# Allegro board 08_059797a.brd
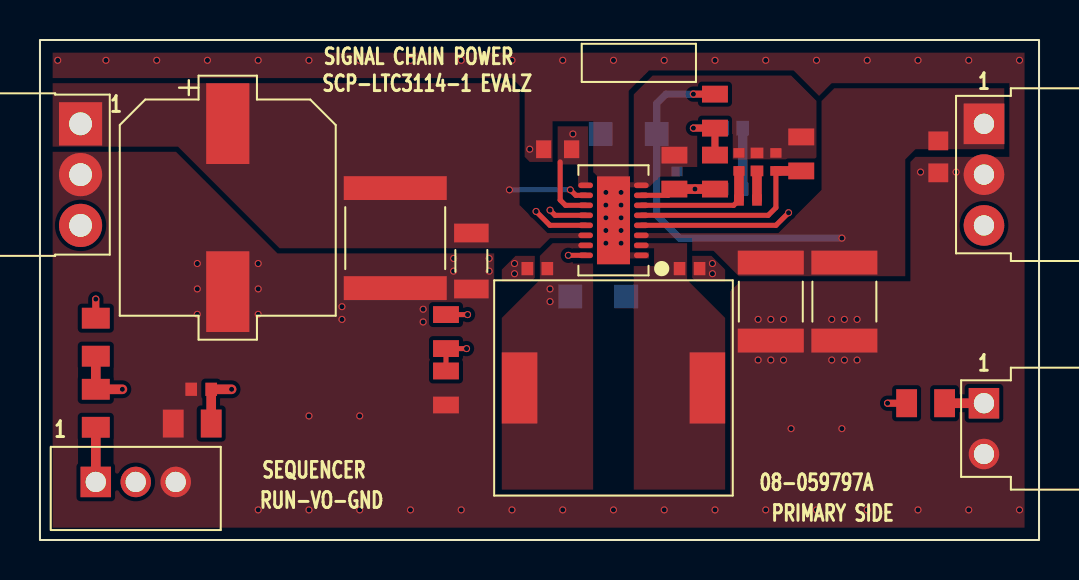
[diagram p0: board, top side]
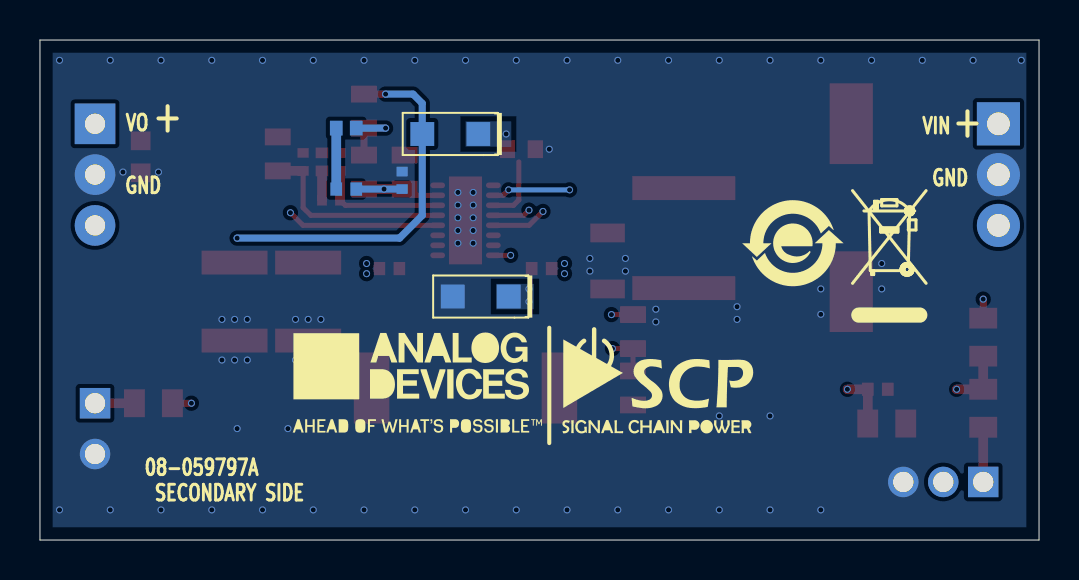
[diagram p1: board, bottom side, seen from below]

Outline 50 x 25 mm; copper layers: TOP, L2_GND, L3_SIGNAL, BOTTOM. Coordinates in mm from the lower left corner of the outline.
Outline path: 0,25 50,25 50,0 0,0 0,25

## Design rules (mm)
constraint set DEFAULT: min track width 0.254

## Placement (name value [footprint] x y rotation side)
C1  68NF  [C0402]  24.89 13.57 180 top
C2  68NF  [C0402]  32.51 13.57 0 top
C3  4.7UF  [C0603]  25.91 19.54 0 top
C4  22UF  [C1812H110]  36.58 11.92 90 top
C5  1UF  [C0603#2]  44.96 19.16 90 top
C6  10uF  [C2220-4]  17.78 15.09 90 top
C7  330UF  [CPLSMSQ406H425]  9.4 16.62 270 top
C8  1uF  [C1206H71]  21.59 13.95 90 top
C9  4700PF  [C0402]  35.43 17 0 top
C10  10PF  [C0402]  34.98 18.9 90 top
C11  0.047UF  [C0402]  36.83 18.9 90 top
C12  1000PF  [C0402]  8.07 7.54 0 top
C13  22UF  [C1812H110]  40.26 11.92 90 top
C14  TBD0402  [C0402]  34.67 17.55 0 bottom
C15  TBD0402  [C0402#2]  31.88 17.98 270 bottom
D1  PMEG2010AEH,115  [SOD123F]  29.46 20.3 0 bottom
D2  PMEG6020ER  [SOD123F]  27.94 12.17 0 bottom
INPUT  PBC03SBAN  [CNTHMHDRRA1X3L300W100H145]  2.03 20.81 270 top
L1  6.8UH  [LSML402W394H201]  28.7 7.6 0 top
NOREF  -  []  90.79 32.31 0 top
NOREF#2  -  []  25.51 46.03 0 top
NOREF#3  -  []  -197.25 -222.03 0 top
NOREF#4  -  []  77.05 131.34 0 top
NOREF#5  -  []  0 0 0 top
NOREF#6  -  []  2.03 20.81 0 top
NOREF#7  -  []  50 25 0 top
NOREF#8  -  []  -197.25 -222.03 0 top
NOREF#9  -  []  0 25 0 top
NOREF#10  -  []  50 0 90 top
NOREF#11  -  []  -137.31 -48.38 0 top
NOREF#12  -  []  0 25 270 top
NOREF#13  -  []  0 0 0 top
NOREF#14  -  []  2.03 20.81 0 top
NOREF#15  -  []  50 0 90 top
NOREF#16  -  []  0 0 0 top
NOREF#17  -  []  50 25 180 top
NOREF#18  -  []  39.83 4.24 0 top
NOREF#19  -  []  0 25 0 top
NOREF#20  -  []  -131.19 155.48 0 top
NOREF#21  -  []  -197.25 -222.03 0 top
NOREF#22  -  []  19.05 7.98 180 bottom
NOREF#23  -  []  7.69 10.93 180 bottom
NOREF#24  -  []  31.4 7.83 180 bottom
NOREF#25  -  []  17.55 11.26 180 bottom
NOREF#26  -  []  12.32 14.84 180 bottom
OUTPUT  PPPC031LGBN-RC  [CNHDRRA1X3H108]  47.24 20.81 270 top
P1  53253-0370  [CNTHMHDR1X3L315W144H224]  2.79 2.9 0 top
R1  2M  [R0805]  33.78 18.4 90 top
R2  499K  [R0805]  31.75 18.4 270 top
R3  10K  [R0805]  38.1 19.3 270 top
R4  27.4K  [R0402]  35.88 18.9 270 top
R5  1MEG  [R0805#2]  2.79 10.14 90 top
R6  0  [R0805#2]  7.62 5.82 0 top
R7  TBD0402  [R0402]  34.67 20.59 180 bottom
R8  49.9  [R0805]  33.78 21.44 90 top
R9  0  [R0805#2]  2.79 6.59 90 top
R10  0  [R0805]  20.32 10.42 270 top
R11  0  [R0805]  20.32 7.6 90 top
R12  0  [R0805#2]  44.32 6.84 0 top
U1  LTC3114MPDHC-1#PBF  [DFN16_5X3_PAD4_4X1_65H31]  28.7 15.98 90 top
VIOC  PPPC021LGBN-RC  [CNTHFHDRRA1X2L220W335H108]  47.24 6.84 270 top

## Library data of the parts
C1 C2 = CAP: User Part Number: UPN; Tolerance: 10; alternate symbols: (); part number: CAP_SM-68NF,16V,10,E035202,C0402; tolerance: 10
C3 = CAP: Tolerance: 10; User Part Number: UPN; alternate symbols: (C0603L_ALT); part number: CAP_SM-4.7UF,6.3V,10,E030256,C0603; tolerance: 10
C4 C13 = CAP: Tolerance: 20; User Part Number: UPN; alternate symbols: (C1812H110L); part number: CAP_SM-22UF,25V,20,E034560,C1812H110; tolerance: 20
C5 = CAP: User Part Number: UPN; Tolerance: 10; alternate symbols: (); part number: CAP_SM-1UF,25V,10,E032748,C0603; tolerance: 10
C6 = CAP: Tolerance: 20; User Part Number: UPN; alternate symbols: (C2220H98L); part number: CAP_SM-10UF,50V,20,E015121,C2220-4; tolerance: 20
C7 = CAPP: User Part Number: UPN; Tolerance: 20; alternate symbols: (); part number: CAPP_SM-330UF,50V,20,E034654,CPLSMSQ406H425; tolerance: 20
C8 = CAP: Tolerance: 10; User Part Number: UPN; alternate symbols: (C1206H71L); part number: CAP_SM-1UF,50V,10,E011257,C1206H71; tolerance: 10
C9 = CAP: User Part Number: UPN; Tolerance: 10; alternate symbols: (C0402L); part number: CAP_SM-4700PF,25V,10,E040088,C0402; tolerance: 10
C10 = CAP: User Part Number: UPN; Tolerance: 5; alternate symbols: (C0402L); part number: CAP_SM-10PF,50V,5,E031797,C0402; tolerance: 5
C11 = CAP: User Part Number: UPN; Tolerance: 10; alternate symbols: (C0402L); part number: CAP_SM-0.047UF,25V,10,E025704,C0402; tolerance: 10
C12 = CAP: User Part Number: UPN; Tolerance: 10; alternate symbols: (); part number: CAP_SM-1000PF,25V,10,E025706,C0402; tolerance: 10
C14 C15 = CAP: User Part Number: UPN; alternate symbols: (C0402L_ALT); part number: CAP_SM-TBD0402,TBD0402,TBD0402,E000381,C0402
D1 = DIOSCHOTTKY: Tolerance: N/A; User Part Number: UPN; alternate symbols: (); part number: DIOSCHOTTKY_SM-PMEG2010AEH,115,20V,N/A,E016182,SOD123F; tolerance: N/A
D2 = DIOSCHOTTKY: Tolerance: N/A; User Part Number: UPN; alternate symbols: (); part number: DIOSCHOTTKY_SM-PMEG6020ER,60V,N/A,E030334,SOD123F; tolerance: N/A
INPUT = CN3P: Tolerance: N/A; User Part Number: UPN; alternate symbols: (CNTHMHDRRA1X3L300W100H145_SCP); part number: CN3P_TH-PBC03SBAN,E034137,CNTHMHDRRA1X3L300W100H145; tolerance: N/A
L1 = IND: Tolerance: 30; User Part Number: UPN; alternate symbols: (); part number: IND_SM-6.8UH,30,E040047,LSML402W394H201; tolerance: 30
OUTPUT = CN3P: User Part Number: UPN; Tolerance: N/A; alternate symbols: (CNHDRRA1X3H108_SCP); part number: CN3P_TH-PPPC031LGBN-RC,E034111,CNHDRRA1X3H108; tolerance: N/A
P1 = CN3P: Tolerance: N/A; User Part Number: UPN; alternate symbols: (); part number: CN3P_TH-53253-0370,E033940,CNTHMHDR1X3L315W144H224; tolerance: N/A
R1 = RES: User Part Number: UPN; Tolerance: 1; alternate symbols: (R0805L); part number: RES_SM-2M,E040097,1/8W,1,R0805; tolerance: 1
R2 = RES: User Part Number: UPN; Tolerance: 1; alternate symbols: (R0805L); part number: RES_SM-499K,E003640,1/8W,1,R0805; tolerance: 1
R3 = RES: User Part Number: UPN; Tolerance: 1; alternate symbols: (R0805L); part number: RES_SM-10K,E003254,1/8W,1,R0805; tolerance: 1
R4 = RES: User Part Number: UPN; Tolerance: 1; alternate symbols: (R0402L); part number: RES_SM-27.4K,E021819,1/10W,1,R0402; tolerance: 1
R5 = RES: User Part Number: UPN; Tolerance: 5; alternate symbols: (); part number: RES_SM-1MEG,E033749,1/8W,5,R0805; tolerance: 5
R6 R9-R12 = RES: User Part Number: UPN; Tolerance: N/A; alternate symbols: (R0805L); part number: RES_SM-0,E030875,1/8W,N/A,R0805; tolerance: N/A
R7 = RES: User Part Number: UPN; alternate symbols: (R0402L,R0402L_ALT); part number: RES_SM-TBD0402,E004049,TBD0402,TBD0402,R0402
R8 = RES: User Part Number: UPN; Tolerance: 1; alternate symbols: (R0805L); part number: RES_SM-49.9,E003412,1/8W,1,R0805; tolerance: 1
U1 = ADLTC3114_1: User Part Number: UPN; Tolerance: N/A; alternate symbols: (); part number: ADLTC3114_1_SM-LTC3114MPDHC-1#PBF,E039955,DFN16_5X3_PAD4_4X1_65H31; tolerance: N/A
VIOC = CN2P: Tolerance: N/A; User Part Number: UPN; alternate symbols: (CNTHFHDRRA1X2L220W335H108_SCP); part number: CN2P_TH-PPPC021LGBN-RC,E034113,CNTHFHDRRA1X2L220W335H108; tolerance: N/A

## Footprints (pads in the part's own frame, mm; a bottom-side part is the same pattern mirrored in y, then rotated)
C0402
  rect 0.584x0.66 smd: 1(-0.5,0) 2(0.5,0)
C0402#2
  rect 0.483x0.559 smd: 1(-0.438,0) 2(0.438,0)
C0603
  rect 0.762x0.889 smd: 1(-0.699,0) 2(0.699,0)
C0603#2
  rect 0.94x0.991 smd: 1(-0.8,0) 2(0.8,0)
C1206H71
  rect 0.94x1.727 smd: 1(-1.4,0) 2(1.4,0)
C1812H110
  rect 1.194x3.302 smd: 1(-1.95,0) 2(1.95,0)
C2220-4
  rect 1.194x5.156 smd: 1(-2.5,0) 2(2.5,0)
CNHDRRA1X3H108
  rect 2.032x2.032 hole 1.016: 1(0,0)
  round 2.032 hole 1.016: 2(2.54,0) 3(5.08,0)
CNTHFHDRRA1X2L220W335H108
  rect 1.524x1.524 hole 1.016: 1(0,0)
  round 1.524 hole 1.016: 2(2.54,0)
CNTHMHDR1X3L315W144H224
  rect 1.524x1.524 hole 1.016: 1(0,0)
  round 1.524 hole 1.016: 2(2,0) 3(4,0)
CNTHMHDRRA1X3L300W100H145
  rect 2.159x2.159 hole 1.143: 1(0,0)
  round 2.159 hole 1.143: 2(2.54,0) 3(5.08,0)
CPLSMSQ406H425
  rect 4.039x2.159 smd: N(4.2,0) P(-4.2,0)
DFN16_5X3_PAD4_4X1_65H31
  oval 0.279x0.737 smd: 1(-1.75,-1.393) 2(-1.25,-1.393) 3(-0.75,-1.393) 4(-0.25,-1.393) 5(0.25,-1.393) 6(0.75,-1.393) 7(1.25,-1.393) 8(1.75,-1.393) 9(1.75,1.393) 10(1.25,1.393) 11(0.75,1.393) 12(0.25,1.393) 13(-0.25,1.393) 14(-0.75,1.393) 15(-1.25,1.393) 16(-1.75,1.393)
  rect 4.394x1.651 smd: PAD(0,0)
LSML402W394H201
  rect 1.778x3.556 smd: 1(-4.7,0) 2(4.7,0)
R0402
  rect 0.533x0.635 smd: 1(-0.45,0) 2(0.45,0)
R0805
  rect 0.838x1.295 smd: 1(-0.85,0) 2(0.85,0)
R0805#2
  rect 1.041x1.397 smd: 1(-0.95,0) 2(0.95,0)
SOD123F
  rect 1.194x1.194 smd: A(1.403,0) C(-1.403,0)

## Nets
GND: C3.1 C4.1 C5.1 C6.1 C7.N(N2) C8.1 C10.2(N2) C11.2(N2) C12.1 C13.1 C15.1 D2.A(P) INPUT.2 OUTPUT.2 P1.3(N3) R2.1 R3.1 R4.1 R6.1 R11.1 U1.1 U1.8 U1.PAD VIOC.2(N2)
VIN: C6.2(N2) C7.P C8.2(N2) INPUT.1 R5.2(N2) U1.10(VIN) U1.14
MODE: R10.2(N2) R11.2(N2) U1.16
RUN: C12.2(N2) R5.1 R6.2(N2) R9.2(N2) U1.4
UNNAMED_2_ADLTC31141_I1_BST1: C1.2(N2) U1.13
UNNAMED_2_ADLTC31141_I1_BST2: C2.2(N2) U1.12
UNNAMED_2_ADLTC31141_I1_FB: C14.1 C15.2(N2) R1.1 R2.2(N2) U1.7
UNNAMED_2_ADLTC31141_I1_LDO: C3.2(N2) D1.C R10.1 U1.9 U1.11
UNNAMED_2_ADLTC31141_I1_PROG: C11.1 R3.2(N2) U1.5
UNNAMED_2_ADLTC31141_I1_SW1: C1.1 D2.C L1.1 U1.15
UNNAMED_2_ADLTC31141_I1_SW2: C2.1 L1.2(N2) U1.2
UNNAMED_2_ADLTC31141_I1_VC: C9.1 C10.1 U1.6
UNNAMED_2_CAP_I21_N2: C14.2(N2) R7.1
UNNAMED_2_CAP_I28_N2: C9.2(N2) R4.2(N2)
UNNAMED_2_CN3P_I25_N1: P1.1 R9.1
UNNAMED_2_RES_I14_N1: R1.2(N2) R7.2(N2) R8.1 R12.1
VIOC: R12.2(N2) VIOC.1
VOUT: C4.2(N2) C5.2(N2) C13.2(N2) D1.A(P) OUTPUT.1 P1.2 R8.2(N2) U1.3

Pads without a net: INPUT 3; OUTPUT 3

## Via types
v1: diameter 0.356, hole 0.254, TOP to BOTTOM, 102 vias

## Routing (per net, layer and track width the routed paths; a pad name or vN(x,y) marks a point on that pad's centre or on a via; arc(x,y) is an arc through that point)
GND:
  vias: v1(0.89,23.98) v1(3.3,23.98) v1(5.84,23.98) v1(7.87,13.82) v1(7.87,12.55) v1(7.87,11.28) v1(8.38,23.98) v1(10.92,23.98) v1(10.92,13.82) v1(10.92,12.55) v1(10.92,11.28) v1(10.92,1.51) v1(13.46,23.98) v1(13.46,6.2) v1(13.46,1.51) v1(15.11,11.67) v1(15.11,11.03) v1(16,23.98) v1(16,6.2) v1(16,1.51) v1(18.54,23.98) v1(18.54,1.51) v1(19.18,11.54) v1(19.18,10.9) v1(20.7,14.08) v1(20.7,13.44) v1(21.08,23.98) v1(21.08,1.51) v1(22.48,14.08) v1(22.48,13.44) v1(23.62,23.98) v1(23.62,1.51) v1(24.51,19.54) v1(26.16,23.98) v1(26.16,1.51) v1(28.32,17.38) v1(28.32,16.75) v1(28.32,16.11) v1(28.32,15.48) v1(28.32,14.84) v1(28.7,23.98) v1(28.7,1.51) v1(29.08,17.38) v1(29.08,16.75) v1(29.08,16.11) v1(29.08,15.48) v1(29.08,14.84) v1(31.24,23.98) v1(31.24,1.51) v1(33.78,23.98) v1(33.78,1.51) v1(35.94,11.03) v1(35.94,9) v1(36.32,23.98) v1(36.32,1.51) v1(36.58,11.03) v1(36.58,9) v1(37.21,11.03) v1(37.21,9) v1(37.59,5.57) v1(38.86,23.98) v1(38.86,1.51) v1(39.62,11.03) v1(39.62,9) v1(40.13,5.57) v1(40.26,11.03) v1(40.26,9) v1(40.89,11.03) v1(40.89,9) v1(41.4,23.98) v1(41.4,1.51) v1(43.94,23.98) v1(43.94,1.51) v1(44.07,18.4) v1(45.85,18.4) v1(46.48,23.98) v1(46.48,1.51) v1(49.02,23.98) v1(49.02,1.51)
VIN: length 14.9
  TOP w0.254: U1.10 26.82,17.23 v1(26.54,17.51)
  TOP w0.356: R5.2 v1(2.79,12.04)
  L3_SIGNAL w0.254: INPUT.1 3.94,18.9 3.94,13.19 v1(2.79,12.04)
  BOTTOM w0.254: v1(26.54,17.51) v1(23.5,17.51)
MODE: length 10
  TOP w0.254: v1(21.35,9.57) R10.2 R11.2 ; U1.16 v1(26.44,14.23)
  L3_SIGNAL w0.254: v1(21.35,9.57) 26.01,14.23 v1(26.44,14.23)
RUN: length 62.8
  TOP w0.254: v1(37.47,16.36) 36.83,15.73 U1.4
  TOP w0.483: R5.1 R9.2 v1(4.12,7.54) ; R6.2 C12.2 v1(9.59,7.54)
  L3_SIGNAL w0.254: v1(4.12,7.54) v1(9.59,7.54) 40.7,7.54 41.53,8.36 41.53,15.73 40.89,16.36 v1(37.47,16.36)
UNNAMED_2_ADLTC31141_I1_BST1: length 6.3
  TOP w0.254: U1.13 25.52,15.73 v1(24.83,16.43)
  L3_SIGNAL w0.254: v1(24.83,16.43) 23.75,15.35 v1(23.75,13.82) v1(23.75,13.32)
UNNAMED_2_ADLTC31141_I1_BST2: length 11.7
  TOP w0.254: U1.12 25.78,16.23 25.53,16.49 v1(25.53,16.49)
  L3_SIGNAL w0.254: v1(33.66,13.82) 33.66,13.57 ; 33.66,13.57 28.45,13.57 v1(25.53,16.49) ; 33.66,13.57 v1(33.66,13.32)
UNNAMED_2_ADLTC31141_I1_FB: length 6.1
  TOP w0.254: R2.2 31.44,17.23 U1.7
  TOP w0.483: R1.1 v1(32.78,17.55) R2.2
  BOTTOM w0.356: C14.1 v1(32.78,17.55) C15.2
UNNAMED_2_ADLTC31141_I1_LDO: length 18
  TOP w0.254: R10.1 v1(21.4,11.27) ; U1.11 26.3,16.73 26.04,17 26.04,18.9
  L3_SIGNAL w0.254: v1(26.67,20.3) 22.48,20.3 21.4,19.22 v1(21.4,11.27)
UNNAMED_2_ADLTC31141_I1_PROG: length 10
  TOP w0.254: U1.5 36.44,16.23 36.83,16.62 C11.1
  TOP w0.483: R3.2 C11.1
UNNAMED_2_ADLTC31141_I1_SW1:
  vias: v1(25.53,12.55) v1(25.53,11.92)
UNNAMED_2_ADLTC31141_I1_VC: length 6.5
  TOP w0.254: U1.6 34.72,16.73 C9.1
  TOP w0.483: C9.1 C10.1
UNNAMED_2_CAP_I21_N2: length 3
  BOTTOM w0.483: R7.1 C14.2
UNNAMED_2_CAP_I28_N2: length 1.5
  TOP w0.483: C9.2 R4.2
UNNAMED_2_CN3P_I25_N1: length 2.7
  TOP w0.483: P1.1 R9.1
UNNAMED_2_RES_I14_N1: length 27.8
  TOP w0.356: v1(32.7,20.59) R8.1 R1.2 ; R12.1 v1(42.42,6.84)
  L3_SIGNAL w0.254: v1(32.7,20.59) 41.49,20.59 42.42,19.66 v1(42.42,6.84)
  BOTTOM w0.356: R7.2 v1(32.7,20.59)
VIOC: length 2
  TOP w0.483: R12.2 VIOC.1
VOUT: length 75.2
  TOP w0.356: R8.2 v1(32.7,22.29)
  L3_SIGNAL w0.254: P1.2 6.83,4.93 43.05,4.93 44.32,6.2 44.32,17.89 OUTPUT.1
  BOTTOM w0.356: v1(32.7,22.29) 31.33,22.29 30.87,21.83 D1.A 30.87,16.23 32,15.09 v1(40.13,15.09)

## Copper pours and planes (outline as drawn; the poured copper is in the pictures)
GND on TOP: 0.64,24.37 49.28,24.37 49.28,0.62 0.64,0.62 0.64,19.41 6.86,19.41 11.94,14.33 22.73,14.33 22.73,2.27 34.54,2.27 34.54,12.43 35.05,12.94 43.56,12.94 43.56,18.9 43.81,19.16 48.51,19.16 48.51,22.84 39.62,22.84 38.99,22.21 37.72,23.48 30.48,23.48 29.46,22.46 29.46,17.89 29.72,17.89 29.72,22.28 30.66,23.22 37.59,23.22 38.86,21.95 38.86,19.03 34.67,19.03 34.67,20.3 32.89,20.3 32.89,18.65 32,18.65 32,18.02 30.86,18.02 30.48,17.63 29.46,17.63 29.46,14.46 30.48,14.46 30.48,14.08 29.46,14.08 29.46,13.82 27.94,13.82 27.94,18.14 27.69,18.4 27.69,20.94 25.65,20.94 25.65,18.9 24.51,18.9 24.26,19.16 24.26,22.46 23.62,23.1 0.64,23.1 ; 2 cut-outs
GND on BOTTOM: 0.64,24.36 49.36,24.36 49.36,0.64 0.64,0.64
GND on L2_GND: 0.64,24.36 49.28,24.36 49.28,0.64 0.64,0.64
GND on L3_SIGNAL: 0.64,24.36 49.36,24.36 49.36,0.64 0.64,0.64 ; 1 cut-out
VIN on TOP: 11.99,14.59 6.91,19.67 0.64,19.67 0.64,22.84 23.5,22.84 24,22.33 24,16.75 25.4,15.35 27.56,15.35 27.56,15.09 25.53,15.09 25.02,14.59
UNNAMED_2_ADLTC31141_I1_BST1 on TOP: 24.77,14.21 23.8,14.21 23.11,13.52 23.11,12.94 24.59,12.94 24.77,13.11
UNNAMED_2_ADLTC31141_I1_BST2 on TOP: 32.64,14.21 33.6,14.21 34.29,13.52 34.29,12.94 32.82,12.94 32.64,13.11
UNNAMED_2_ADLTC31141_I1_LDO on TOP: 25.91,20.68 27.43,20.68 27.43,17.63 26.92,17.63 26.92,18.65 26.89,18.74 26.8,18.78 25.91,18.78
UNNAMED_2_ADLTC31141_I1_LDO on BOTTOM: 28.7,20.94 28.7,19.67 26.42,19.67 26.42,20.94
UNNAMED_2_ADLTC31141_I1_SW1 on TOP: 25.65,14.84 27.69,14.84 27.69,14.59 26.67,14.59 26.67,13.82 27.69,13.82 27.69,2.52 23.11,2.52 23.11,11.1 24.98,12.97 25.01,13.01 25.02,13.06 25.02,14.21
UNNAMED_2_ADLTC31141_I1_SW1 on BOTTOM: 27.18,12.81 27.18,11.54 25.27,11.54 25.27,12.81
UNNAMED_2_ADLTC31141_I1_SW2 on TOP: 29.72,14.84 32.39,14.84 32.39,13.01 32.68,12.72 34.29,11.1 34.29,2.52 29.72,2.52 29.72,13.7 30.73,13.7 30.73,14.59 29.72,14.59
VOUT on TOP: 39.75,22.59 48.26,22.59 48.26,19.54 43.81,19.54 43.31,19.03 43.31,13.19 34.98,13.19 33.71,14.46 32.64,14.46 32.64,15.09 29.72,15.09 29.72,15.35 36.96,15.35 39.12,17.51 39.12,21.95

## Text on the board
Ref Des/Silkscreen Bottom: GND | VIN | 08-059797A | VO | +
User.Comments: 4.    RoHS COMPLIANCE: ASSEMBLY VENDOR SHOULD ASSURE COMPLIANCE | WITH LEAD-FREE AND RoHS PCB ASSEMBLY STANDARDS (EU RoHS | DIRECTIVE 2002/95/EC).
Ref Des/Silkscreen Top: SEQUENCER | RUN-VO-GND | SIGNAL CHAIN POWER | SCP-LTC3114-1 EVALZ
ROOT_NUMBER: 059797
DIMENSION: REF | SEE FAB NOTES 15 | DIA MAX
PAGE_OUTLINE: N/A | A.CAUILAN | K.JABATAN | L EVANGELIO | J.VIERNES | 05DEC18 | 04DEC19 | 11DEC19 | A | SCP-LTC3114-1 EVALZ | EVALUATION BOARD | -059797
User.15: ROHS COMPLIANCE NOTE:  (Required for Customer Boards) Add to top of MATERIALS | ENIG (Electroless Nickel/Immersion Gold) | PER IPC-4552 LATEST REVISION | HOMOGENOUS MATERIALS IN THIS BOARD SHALL BE COMPLIANT | THE EU RoHS DIRECTIVE 2002/95/EC | INTERNAL LAYERS 1 OZ. COPPER. | 15.    THRU VIAS TO BE FILLED WITH SOLDERMASK.
User.17: L2 GND | 08-      -07
User.18: L3 SIGNAL | 08-      -08
User.23: 2 | A
User.27: 2 | A
User.45: 2 | FIGURE | SIZE | 10.0 | 40.0 | 45.0 | PLATED | FINISHED HOLES IN MILS | ALL UNITS ARE IN MILS | QTY | 102 | 8 | 3 | TOLERANCE/NOTES | EVALUATION BOARD | A
